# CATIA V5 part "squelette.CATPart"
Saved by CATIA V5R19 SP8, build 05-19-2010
Part number: squelette
Bounding box of the stored display mesh (mm): x 0 to 637.027, y -557.938 to -323.498, z -186.48 to -75.472
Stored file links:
  G:\EU_thinkMotion\CFAO_2010\MMS_groupe1\MMS_groupe1\A reprendre\OK\rdeneffle\squelette.CATPart
  G:\EU_thinkMotion\CFAO_2010\MMS_groupe1\MMS_groupe1\A reprendre\OK\rdeneffle\systeme d'ouverture de porte de voiture.CATProduct
  G:\EU_thinkMotion\CFAO_2010\MMS_groupe1\MMS_groupe1\A reprendre\OK\rdeneffle\carosserie.CATPart
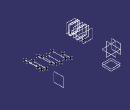
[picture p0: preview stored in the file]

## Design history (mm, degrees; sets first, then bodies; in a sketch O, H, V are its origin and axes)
Body1 (main body)
  Plane1: type Offset, RefPlane zx-plane, Offset 376.765, reversed
  Plane2: type Offset, RefPlane zx-plane, Offset 557.938, reversed
  Plane3: type Offset, RefPlane zx-plane, Offset 407.708, reversed
  Plane4: type Offset, RefPlane zx-plane, Offset 425.353, reversed
  Plane5: type Offset, RefPlane zx-plane, Offset 509.351, reversed
  Plane6: type Offset, RefPlane zx-plane, Offset 527.015, reversed
  Point1: type OnPlane, Support Plane1, H 0, V -75.472, Direction (-1, 0, 0)
  Point2: type OnPlane, Support Plane2, H 0, V -75.472, Direction (-1, 0, 0)
  Line1: type PtPt, FirstPoint Point1, SecondPoint Point2
  Point3: type OnPlane, Support Plane1, H -259.016, V -169.856, Direction (-1, 0, 0)
  Point4: type OnPlane, Support Plane2, H -259.016, V -169.856, Direction (-1, 0, 0)
  Line2: type PtPt, FirstPoint Point4, SecondPoint Point3
  Plane7: type Offset, RefPlane zx-plane, Offset 323.498, reversed
  Point5: type OnPlane, Support Plane7, H -243.085, V -142.975, Direction (-1, 0, 0)
  Point6: type OnPlane, Support Plane4, H -243.085, V -142.975, Direction (-1, 0, 0)
  Line3: type PtPt, FirstPoint Point5, SecondPoint Point6
  Point7: type OnPlane, Support Plane1, H -320.85, V -186.48, Direction (-1, 0, 0)
  Point8: type OnPlane, Support Plane1, H -395.42, V -169.69, Direction (-1, 0, 0)
  Point9: type OnPlane, Support Plane1, H -458.063, V -127.919, Direction (-1, 0, 0)
  Point10: type OnPlane, Support Plane1, H -523.121, V -158.391, Direction (-1, 0, 0)
  Point11: type OnPlane, Support Plane1, H -589.419, V -135.823, Direction (-1, 0, 0)
  Point12: type OnPlane, Support Plane1, H -637.027, V -84.538, Direction (-1, 0, 0)
  Point13: type OnPlane, Support Plane2, H -320.85, V -186.48, Direction (-1, 0, 0)
  Point14: type OnPlane, Support Plane2, H -395.42, V -169.69, Direction (-1, 0, 0)
  Point15: type OnPlane, Support Plane2, H -458.063, V -127.919, Direction (-1, 0, 0)
  Point16: type OnPlane, Support Plane2, H -523.121, V -158.391, Direction (-1, 0, 0)
  Point17: type OnPlane, Support Plane2, H -589.419, V -135.823, Direction (-1, 0, 0)
  Point18: type OnPlane, Support Plane2, H -637.027, V -84.538, Direction (-1, 0, 0)
  Line4: type PtPt, FirstPoint Point13, SecondPoint Point7
  Line5: type PtPt, FirstPoint Point14, SecondPoint Point8
  Line6: type PtPt, FirstPoint Point15, SecondPoint Point9
  Line7: type PtPt, FirstPoint Point16, SecondPoint Point10
  Line8: type PtPt, FirstPoint Point17, SecondPoint Point11
  Line9: type PtPt, FirstPoint Point18, SecondPoint Point12
  Plane8: type Offset, RefPlane xy-plane, Offset 171.7, reversed
  Plane9: type Offset, RefPlane yz-plane, Offset 68.503, reversed
  Plane10: type Offset, RefPlane zx-plane, Offset 412.408, reversed
  Plane11: type Offset, RefPlane zx-plane, Offset 522.315, reversed
  Plane12: type Offset, RefPlane Plane5, Offset 5.462
  Plane13: type Offset, RefPlane Plane4, Offset 34.145, reversed
  Plane14: type Offset, RefPlane yz-plane, Offset 725.678
  Plane15: type Offset, RefPlane xy-plane, Offset 197.331, reversed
